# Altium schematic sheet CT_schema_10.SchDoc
size 382 x 278 mm
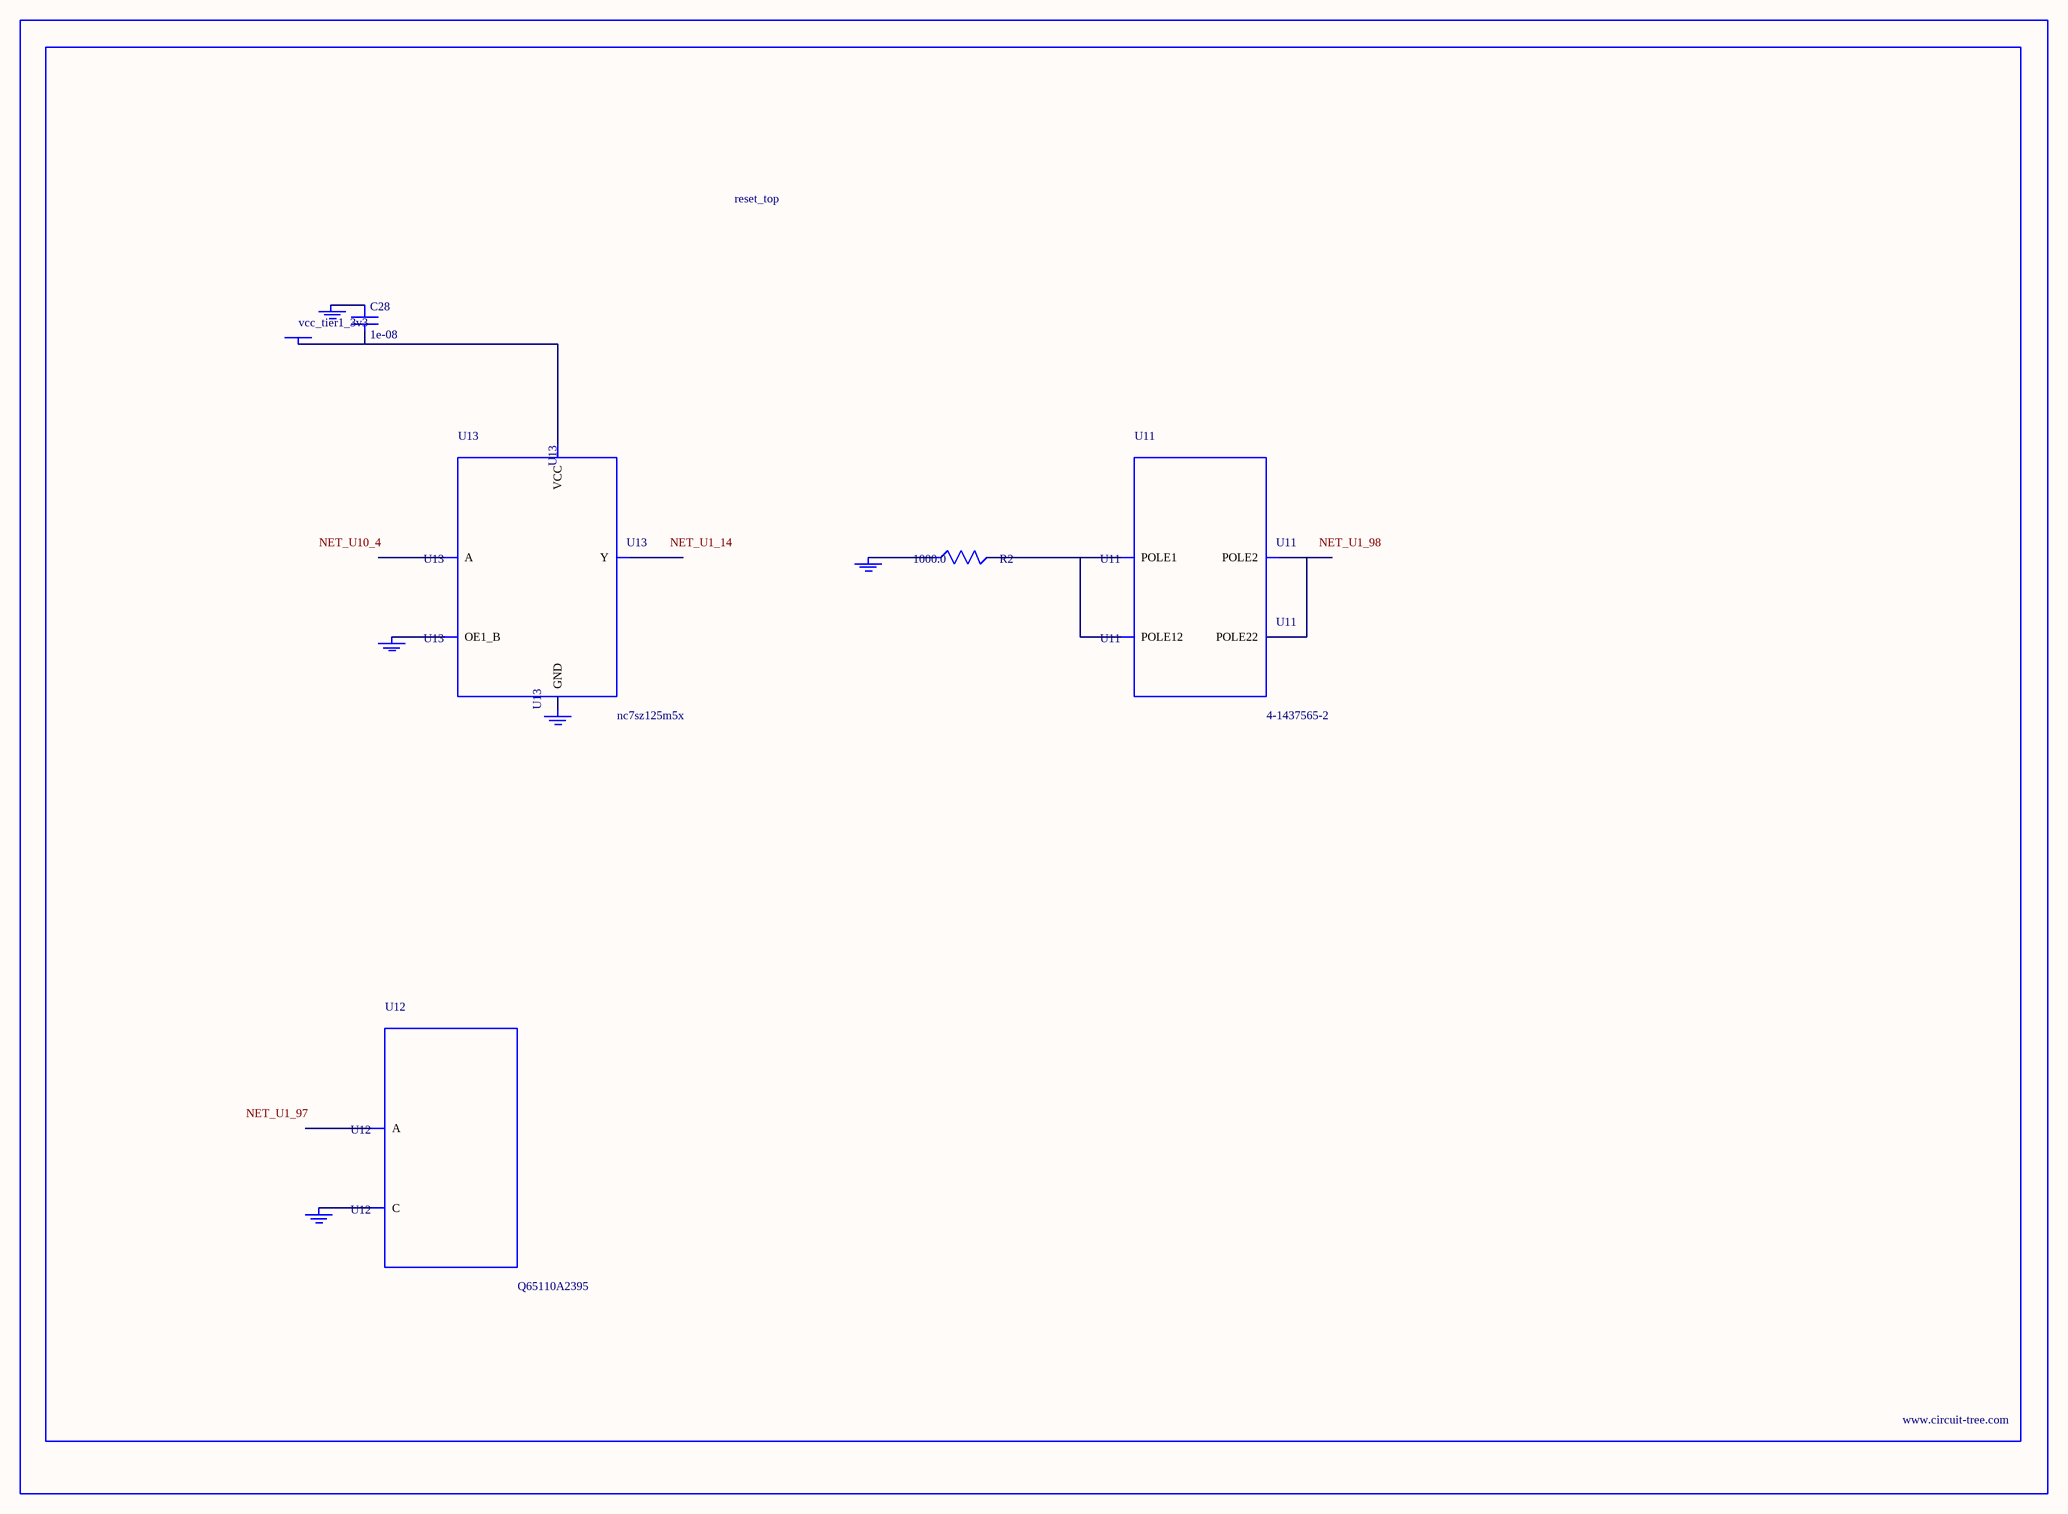
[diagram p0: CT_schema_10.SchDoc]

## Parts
BORDER9  (no value)
C28  1e-08  [C0402]
GND_INSTANCE_9_0  (no value)
GND_INSTANCE_9_1  (no value)
GND_INSTANCE_9_2  (no value)
GND_INSTANCE_9_3  (no value)
GND_INSTANCE_9_4  (no value)
POWER_INSTANCE_9_0  vcc_tier1_3v3
R2  1000.0  [R0603]
U11  4-1437565-2  [SW_4-1437565-2]
U12  Q65110A2395  [LGM67K-G1J2-24-Z]
U13  nc7sz125m5x  [NC7SZ125M5X]

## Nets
NetC28_1: C28.1 GND_INSTANCE_9_2.0(GND)
NetC28_2: C28.2 POWER_INSTANCE_9_0.0(PWR) U13.5(VCC)
NetGND_INSTANCE_9_0_0: GND_INSTANCE_9_0.0(GND) R2.1
NetGND_INSTANCE_9_1_0: GND_INSTANCE_9_1.0(GND) U12.C
NetGND_INSTANCE_9_3_0: GND_INSTANCE_9_3.0(GND) U13.1(OE1_B)
NetGND_INSTANCE_9_4_0: GND_INSTANCE_9_4.0(GND) U13.3(GND)
NetR2_2: R2.2 U11.1(POLE1) U11.2(POLE12)
NetU11_3: U11.3(POLE2) U11.4(POLE22)

Not connected (* = marked no-connect by the designer): U12 A; U13 2(A) 4(Y)

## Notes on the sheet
- Labels drawn without touching a wire or pin: NET_U1_14, NET_U1_97, NET_U1_98, NET_U10_4

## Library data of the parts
BORDER9 = BORDER_PAGE9
C28 = C0402C103K3RAC
GND_INSTANCE_9_0-GND_INSTANCE_9_4 = GND
POWER_INSTANCE_9_0 = PWR
R2 = RC0603JR-071KL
